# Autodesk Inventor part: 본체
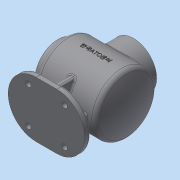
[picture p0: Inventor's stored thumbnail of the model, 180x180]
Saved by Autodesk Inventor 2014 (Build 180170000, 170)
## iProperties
Created: 2023-01
Part Number: 본체
Material: 일반
Document SubType Name: Modeling
Designer: dg
Density: 1 g/cm^3
Appearance: 기본값
Author: dg
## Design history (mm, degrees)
sketch "스케치1"
  geometry: L1 (-61, 0)-(61, 0); L2 (50.087, 50)-(-51, 50); L3 (-51, 50)-(-51, 38); L4 (-51, 38)-(-61, 38); L5 (-61, 38)-(-61, 0); L6 (-44, 27)-(-44, 45); L7 (-44, 45)-(46.83, 45); L8 (-61, 27)-(-44, 27); A1 r 120 centre (-59, 0) between (61, 0) and (50.087, 50); A2 r 115 centre (-59, 0) between (56, 0) and (46.83, 45); 2 further points
  constraints: 16 end point, 4 point on circle, 3 point on line, 2 centre point, 2 horizontal, 2 parallel, 2 perpendicular, 1 coincident, 1 midpoint, 1 vertical
  dimensions: "d0" = 122 distance of L1.start L1.end; "d1" = 120 radius of A1; "d2" = 100 diameter of L2 L1; "d3" = 76 diameter of L4 L1; "d5" = 5 radial gap between concentric circles of A1 A2; "d6" = 5 distance between parallel lines of L2 L7; "d7" = 51 distance from line of L3 point (0, 0); "d8" = 54 diameter of L8 L1; "d9" = 17 distance of L8.start L6.start
revolve "회전1" sketch "스케치1" stored, may be unused: angle "d10" = 90 deg
fillet "모깎기1" dims "d11" = 8
node "작업 평면1"
sketch "스케치2"
  geometry: L1 (-17, 0)-(17, 0); L2 (-17, -46)-(17, -46); L3 (17, 46)-(-17, 46); A1 r 46 centre (-17, 0) between (-17, 46) and (-17, -46); A2 r 46 centre (17, 0) between (17, -46) and (17, 46); 2 further points
  constraints: 8 end point, 4 point on circle, 4 tangent, 2 centre point, 1 coincident, 1 horizontal, 1 midpoint, 1 parallel
  dimensions: "d14" = 92 distance between parallel lines of L2 L3; "d15" = 126 dimension on A2 A1
extrude "돌출1" join sketch "스케치2" distance "d23" = 10; taper "d24" = 0 deg
node "작업 평면3"
sketch "스케치3"
  geometry: L1 (51, 42)-(51, -42) reference; L2 (-52.243, -45)-(-52.243, 45) reference; C1 r 38 at (0, 0); 2 further points
  constraints: 1 centre point, 1 coincident, 1 horizontal alignment, 1 midpoint
  dimensions: "d26" = 76 diameter of C1; "d93" = 51 distance from line of point (0, 0) L1
extrude "돌출2" join sketch "스케치3" stored distance "d27" = 10; taper "d28" = 0 deg
hole "구멍1" diameter "d31" = 54; stored, may be unused: countersink angle "d35" = 90 deg, drill point angle "d37" = 118 deg; dims "d29" = 10, "d30" = 10, "d32" = 6, "d33" = 4, "d34" = 2, "d36" = 53.5
sketch "스케치4"
  geometry: L1 (-5, 35)-(5, 35); L2 (5, 35)-(5, -35); L3 (5, -35)-(-5, -35); L4 (-5, -35)-(-5, 35); 3 further points
  constraints: 8 end point, 2 midpoint, 2 parallel, 1 horizontal, 1 horizontal alignment, 1 perpendicular, 1 vertical alignment
  dimensions: "d38" = 10 distance of L1.start L1.end; "d39" = 70 distance of L3.end L1.start
extrude "돌출3" join sketch "스케치4" stored distance "d40" = 10; taper "d41" = 0 deg
sketch "스케치5"
  geometry: L1 (-5, -70)-(-5, -35.707) reference; L2 (-43, -50)-(44.827, -50) reference; L3 (-43, -50)-(44.827, -50) reference; L4 (5, -70)-(5, -35.707) reference; L5 (-34.641, -50)-(-40, -70); L6 (-17, -70)-(-63, -70) reference; L7 (46.83, -45)-(-44, -45) reference; L8 (17, -80)-(-17, -80) reference; L9 (0, -45)-(0, -80); 1 further point
  constraints: 4 end point, 2 midpoint, 2 point on line
  dimensions: "d42" = 105 deg angle of L6 L5; "d43" = 40 distance from line of L9 L5.end; "d44" = 23 distance of L6.end L5.end
feature "리브1" sketch "스케치5" dims "d45" = 1, "d46" = 10, "d47" = 0, "d48" = 0, "d49" = 1, "d50" = 1
fillet "모깎기2" dims "d51" = 3
fillet "모깎기3" dims "d52" = 3
fillet "모깎기4" dims "d53" = 3
sketch "스케치6"
  geometry: C1 r 4.5 at (-30, 30); C2 r 4.5 at (30, 30); C3 r 4.5 at (30, -30); C4 r 4.5 at (-30, -30); 1 further point
  constraints: 4 centre point, 3 equal radius, 2 vertical alignment
  dimensions: "d54" = 30 horizontal distance of point (0, 0) C1.centre; "d55" = 60 distance of C4.centre C1.centre; "d56" = 30 horizontal distance of point (0, 0) C1.centre; "d57" = 30 horizontal distance of point (0, 0) C2.centre; "d58" = 30 horizontal distance of point (0, 0) C2.centre; "d59" = 30 horizontal distance of C3.centre point (0, 0); "d60" = 9 diameter of C1
extrude "돌출4" cut sketch "스케치6" distance "d61" = 10; taper "d62" = 0 deg
chamfer "모따기1" distance "d63" = 1; stored, may be unused: second distance "d64" = 2, angle "d65" = 45 deg
sketch "스케치7"
  geometry: C1 r 38 at (0, 0) reference; 1 further point
  constraints: 1 vertical alignment
  dimensions: "d66" = 32.5 distance of C1.centre point (0, 32.5)
hole "구멍2" sketch "스케치7" at (0, 32.5) diameter "d67" = 3.242; stored, may be unused: countersink angle "d71" = 82 deg, drill point angle "d73" = 118 deg; dims "d68" = 8, "d69" = 3.023, "d70" = 2, "d72" = 10
sketch "스케치8"
  geometry: C1 r 38 at (0, 0) reference; 1 further point
  constraints: 1 vertical alignment
  dimensions: "d77" = 32.5 distance of point (0, 32.5) C1.centre
hole "구멍3" sketch "스케치8" at (0, 32.5) diameter "d78" = 3.242; stored, may be unused: countersink angle "d82" = 82 deg, drill point angle "d84" = 118 deg; dims "d79" = 8, "d80" = 3.023, "d81" = 2, "d83" = 10
fillet "모깎기5" dims "d88" = 3
node "작업 평면4"
sketch "스케치10"
  geometry: L1 (-60.544, -38)-(-60.544, 38) reference; L2 (63.456, -80)-(17.456, -80) reference; 2 further points
  constraints: 1 other
  dimensions: "d89" = 63 distance from line of L1 point (2.456, 0); "d90" = 80 distance from line of L2 point (2.456, 0)
feature "엠보싱1" sketch "스케치10" dims "d0" = 122, "d1" = 120, "d2" = 100, "d3" = 76, "d5" = 5, "d6" = 5, "d7" = 51, "d8" = 54, "d9" = 17, "d14" = 92, "d15" = 126, "d91" = 0.5, "d92" = 0
fillet "모깎기6" dims "d94" = 3
node "솔리드1"
mirror "대칭1"
pattern_circular "원형 패턴1" dims angle "d75" = 360 deg
pattern_circular "원형 패턴2" dims angle "d86" = 360 deg
node "투영된 루프1"
other parameters: "d25" = 144
